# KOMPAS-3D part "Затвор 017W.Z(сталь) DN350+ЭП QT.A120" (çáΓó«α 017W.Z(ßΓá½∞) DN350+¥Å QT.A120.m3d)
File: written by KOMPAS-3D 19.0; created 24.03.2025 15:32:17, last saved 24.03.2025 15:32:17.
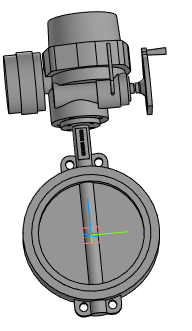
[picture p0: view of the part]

Document properties: Полное имя файла: Затвор 017W.Z(сталь) DN350+ЭП QT.A120.a3d

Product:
- Part/product: Затвор 017W.Z(сталь) DN350+ЭП QT.A120
    Масса: 196.263

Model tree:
1. Операция без истории:1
